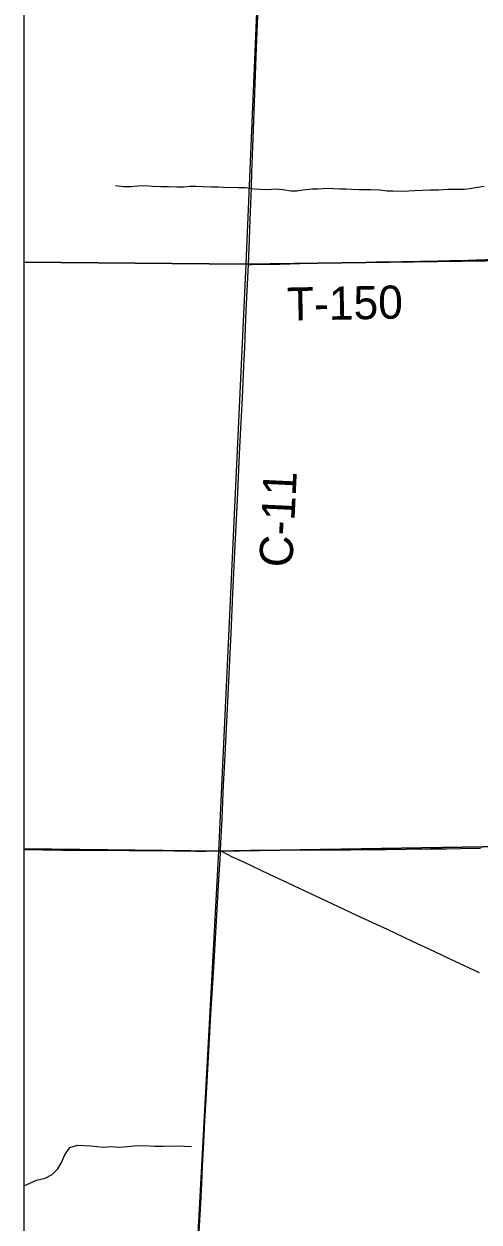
# Model space of a CAD drawing. Extents: x 0 to 34, y 0 to 22.
# Drawn here: x 2.1 to 2.489, y 17.914 to 18.94 of the extents above; entities that cross this region are included whole.
import ezdxf

# ---------------------------------------------------------------- set-up
doc = ezdxf.new("R2010")
doc.units = 0
for name, color, linetype in [('GM_X_Corporation', 7, 'Continuous'), ('GM_X_County_Road', 7, 'Continuous'), ('GM_X_County_Road_Text', 7, 'Continuous'), ('GM_X_Minor_River', 7, 'Continuous'), ('GM_X_Township_Road', 7, 'Continuous'), ('GM_X_Township_Road_Text', 7, 'Continuous')]:
    doc.layers.add(name, color=color, linetype=linetype)

msp = doc.modelspace()

# ---------------------------------------------------------------- linework, layer by layer
at = {"layer": 'GM_X_Corporation'}
for points in [[(2.1, 20.7197), (2.1, 14.1)], [(2.1, 20.7197), (2.1, 17.7319)]]:
    msp.add_lwpolyline(points, dxfattribs=at)
for points in [[(2.1, 19.2421), (2.1, 18.7363), (2.2901, 18.7344), (2.3115, 19.2398)], [(2.3115, 19.2398), (2.8138, 19.2434), (2.8021, 18.7416), (2.2901, 18.7344)], [(2.8021, 18.7416), (2.7708, 18.2399), (2.2668, 18.2317), (2.2901, 18.7344)], [(2.1, 18.7363), (2.1, 18.2336), (2.2668, 18.2317), (2.2901, 18.7344)], [(2.2668, 18.2317), (2.7708, 18.2399), (2.7445, 17.7368), (2.7189, 17.7365), (2.2397, 17.7297)], [(2.1, 18.2336), (2.1, 17.7306), (2.2239, 17.7296), (2.2397, 17.7297), (2.2668, 18.2317)]]:
    msp.add_lwpolyline(points, close=True, dxfattribs=at)
at = {"layer": 'GM_X_County_Road'}
for points in [[(2.2921, 18.7341), (2.2929, 18.7557), (2.2936, 18.7728), (2.2946, 18.7998), (2.2951, 18.8132), (2.2958, 18.8346), (2.2973, 18.8731), (2.2981, 18.8967), (2.2991, 18.9197), (2.2998, 18.9402), (2.3014, 18.9747), (2.3023, 18.9989), (2.3044, 19.0442), (2.3061, 19.0834), (2.3073, 19.1095), (2.3078, 19.1256), (2.3079, 19.1272), (2.3082, 19.1327), (2.3089, 19.1473), (2.3105, 19.1809), (2.3118, 19.2107), (2.313, 19.2392)], [(2.2683, 18.2319), (2.2686, 18.2387), (2.2696, 18.259), (2.2709, 18.2888), (2.2719, 18.3083), (2.2728, 18.3254), (2.2744, 18.3596), (2.2761, 18.3953), (2.2772, 18.4185), (2.2788, 18.4521), (2.2807, 18.4937), (2.2828, 18.5322), (2.2846, 18.5716), (2.2857, 18.594), (2.287, 18.6197), (2.2882, 18.6477), (2.2889, 18.6629), (2.2897, 18.6796), (2.2903, 18.6949), (2.2921, 18.7341)], [(2.2683, 18.2319), (2.2715, 18.2319), (2.2792, 18.2322), (2.2935, 18.2325), (2.3019, 18.2325), (2.3081, 18.2325), (2.3302, 18.2328), (2.3408, 18.2327), (2.3544, 18.2328), (2.3709, 18.2328), (2.3796, 18.2328), (2.3939, 18.233), (2.4101, 18.2332), (2.4268, 18.2334), (2.448, 18.2336), (2.4548, 18.2337), (2.4613, 18.2338), (2.474, 18.2341), (2.4907, 18.2344)], [(2.1, 18.2331), (2.1324, 18.2326), (2.1558, 18.2325), (2.1899, 18.2322), (2.2285, 18.2319), (2.2467, 18.2317), (2.256, 18.2318), (2.265, 18.2319), (2.2683, 18.2319)], [(2.4898, 18.1276), (2.4769, 18.1336), (2.4648, 18.1393), (2.4515, 18.1455), (2.4324, 18.1544), (2.411, 18.1646), (2.3854, 18.1764), (2.3685, 18.1844), (2.3406, 18.1974), (2.3266, 18.204), (2.3097, 18.2119), (2.2881, 18.2222), (2.2786, 18.2267), (2.2683, 18.2319)]]:
    msp.add_lwpolyline(points, dxfattribs=at)
at = {"layer": 'GM_X_Minor_River'}
for points in [[(2.2307, 18.8004), (2.2236, 18.8006), (2.2171, 18.8008), (2.2101, 18.8011), (2.2037, 18.8015), (2.1974, 18.8012), (2.1914, 18.8008), (2.1853, 18.8007), (2.1783, 18.8015)], [(2.494, 18.8011), (2.4863, 18.7997), (2.4815, 18.7991), (2.4768, 18.7984), (2.47, 18.7984), (2.4628, 18.7983), (2.4548, 18.7979), (2.448, 18.7978), (2.4408, 18.7975), (2.4341, 18.7973), (2.4292, 18.7971), (2.422, 18.7968), (2.4156, 18.797), (2.4107, 18.7971), (2.4046, 18.7977), (2.3968, 18.7981), (2.3917, 18.7981), (2.3868, 18.7982), (2.3804, 18.7984), (2.3754, 18.7988), (2.3701, 18.7988), (2.3648, 18.799), (2.3597, 18.7994), (2.3514, 18.7987), (2.3463, 18.7986), (2.3387, 18.7979), (2.3336, 18.7969), (2.3286, 18.797), (2.3216, 18.7982), (2.3146, 18.7986), (2.309, 18.798), (2.302, 18.7983), (2.297, 18.7987), (2.2895, 18.7997), (2.2836, 18.7999), (2.2709, 18.8), (2.266, 18.8004), (2.2605, 18.8004), (2.2531, 18.8008), (2.247, 18.8009), (2.2421, 18.8011), (2.2368, 18.8005), (2.2307, 18.8004)], [(2.1, 17.945), (2.1043, 17.9472), (2.1108, 17.9498), (2.118, 17.9515), (2.1242, 17.9549), (2.129, 17.9596), (2.1319, 17.9645), (2.1349, 17.9715), (2.1393, 17.978), (2.1458, 17.98), (2.1569, 17.9793)], [(2.1569, 17.9793), (2.1678, 17.9782), (2.1746, 17.9788), (2.1818, 17.9783), (2.1882, 17.9787), (2.1947, 17.9792), (2.2006, 17.9796), (2.2072, 17.9793), (2.2121, 17.9789), (2.2191, 17.9791), (2.2324, 17.9794), (2.2373, 17.9791), (2.2435, 17.9787)]]:
    msp.add_lwpolyline(points, dxfattribs=at)
at = {"layer": 'GM_X_Township_Road'}
for points in [[(2.2921, 18.7341), (2.2951, 18.7342), (2.319, 18.7346), (2.3529, 18.7355), (2.3849, 18.736), (2.4011, 18.7364), (2.4235, 18.7367), (2.4542, 18.7373), (2.4645, 18.7375), (2.4732, 18.7377), (2.4869, 18.7381), (2.4888, 18.7382)], [(2.4888, 18.7382), (2.5105, 18.739), (2.5474, 18.7401), (2.5599, 18.7403), (2.5773, 18.7404), (2.595, 18.7406), (2.6099, 18.7406), (2.6139, 18.7406), (2.646, 18.7407), (2.6612, 18.7408), (2.6702, 18.7409), (2.6786, 18.7409), (2.719, 18.741), (2.7454, 18.741), (2.7566, 18.741), (2.7787, 18.741), (2.7864, 18.741), (2.7983, 18.7412), (2.8034, 18.7413)], [(2.2404, 17.7306), (2.2404, 17.7319), (2.2416, 17.7513), (2.2422, 17.7634), (2.2452, 17.8202), (2.2469, 17.8479), (2.2492, 17.8913), (2.2503, 17.9109), (2.2513, 17.9301), (2.2521, 17.9472), (2.2528, 17.9615), (2.2536, 17.977), (2.2548, 18.0006), (2.2561, 18.0239), (2.26, 18.0922), (2.2611, 18.1096), (2.2619, 18.1235), (2.2627, 18.1369), (2.2653, 18.1819), (2.2667, 18.2073), (2.2679, 18.2247), (2.2683, 18.231), (2.2683, 18.2319)]]:
    msp.add_lwpolyline(points, dxfattribs=at)

# ---------------------------------------------------------------- texts
at = {"layer": 'GM_X_County_Road_Text'}
msp.add_text('C-11', height=0.02841, rotation=87.2589, dxfattribs=at).set_placement((2.3296, 18.4743))
at = {"layer": 'GM_X_Township_Road_Text'}
msp.add_text('T-150', height=0.02841, rotation=1.1203, dxfattribs=at).set_placement((2.3253, 18.686))

doc.saveas('drawing.dxf')
